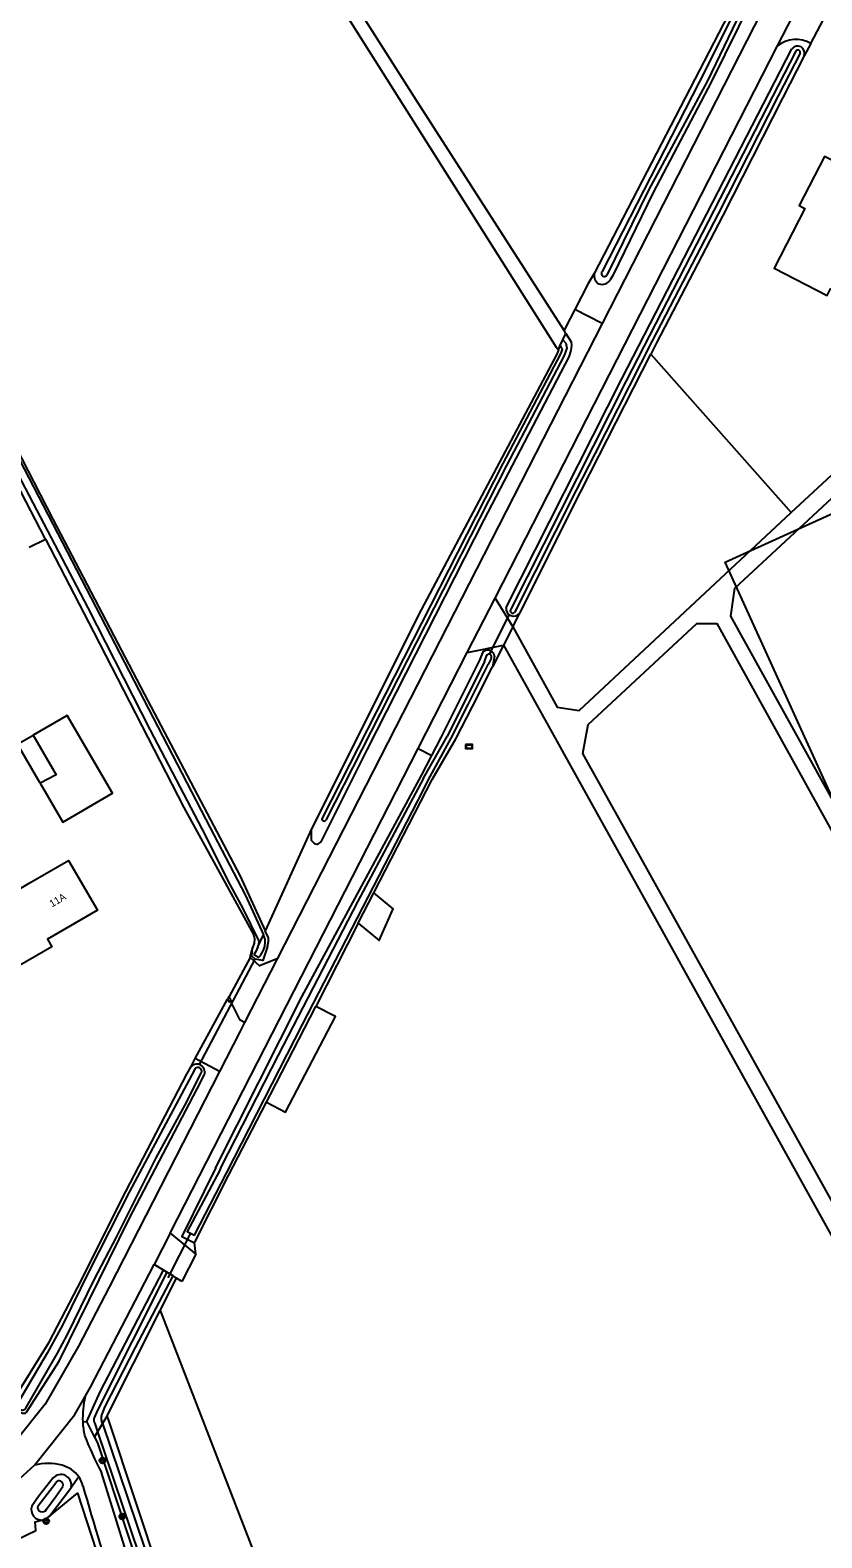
# Model space of a CAD drawing. Extents: x 141000 to 143000, y 400580 to 403500.
# Drawn here: x 141610 to 141719.9, y 402801.5 to 403010.7 of the extents above; entities that cross this region are included whole.
import ezdxf

# ---------------------------------------------------------------- set-up
doc = ezdxf.new("R2010")
doc.units = 0
for name, color, linetype in [('gg-afsc-draadraster', 7, 'Continuous'), ('gg-afsc-erfafscheiding', 7, 'Continuous'), ('gg-afsc-muur', 7, 'Continuous'), ('gg-anno-huisnummerreeks BGT', 7, 'Continuous'), ('gg-bbg-bijgebouw', 7, 'Continuous'), ('gg-bbg-hoofdgebouw', 7, 'Continuous'), ('gg-bbg-luifel en loopbrug', 7, 'Continuous'), ('gg-knt-bronhoudergrens', 7, 'Continuous'), ('gg-knt-onverhard', 7, 'Continuous'), ('gg-knt-verharding', 7, 'Continuous'), ('gg-knt-verharding nz', 7, 'Continuous'), ('gg-kntw-bovenkant insteek waterloop', 7, 'Continuous'), ('gg-kntw-waterlijn', 7, 'Continuous'), ('gg-kwrk-duiker nz buis', 7, 'Continuous'), ('gt-bbg-plantopografie pand', 7, 'Continuous'), ('gt-grn-groengrens', 7, 'Continuous'), ('gt-grn-vlakafsluiter', 7, 'Continuous'), ('gt-grn-weggrens', 7, 'Continuous'), ('gt-symb-boom', 7, 'Continuous'), ('gt-symb-informatiebord', 7, 'Continuous')]:
    doc.layers.add(name, color=color, linetype=linetype)

# ---------------------------------------------------------------- blocks, each defined once
blk = doc.blocks.new('gt0-IBORD')
at = {"layer": 'gt-symb-informatiebord'}
blk.add_lwpolyline([(-0.5, 0.29), (-0.5, -0.29), (0.5, -0.29), (0.5, 0.29), (-0.5, 0.29)], dxfattribs=at)
blk.add_lwpolyline([(-0.42, -0.21), (0.42, -0.21), (0.42, 0.21), (-0.42, 0.21)], close=True, dxfattribs=at)
blk = doc.blocks.new('gt0-BOOM')
at = {"layer": 'gt-symb-boom'}
for radius in [0.4, 0.2]:
    blk.add_circle((0, 0), radius, dxfattribs=at)

msp = doc.modelspace()

# ---------------------------------------------------------------- linework, layer by layer
at = {"layer": 'gg-afsc-draadraster'}
for p, q in [((141713.99, 403026.62), (141688.28, 402976.92)), ((141685.59, 402971.93), (141684.31, 402969.43))]:
    msp.add_line(p, q, dxfattribs=at)
for points in [[(141688.28, 402976.92), (141687.42, 402975.51), (141685.59, 402971.93)], [(141612.7, 402804.54), (141616.6, 402807.72), (141625.72, 402779.73), (141633.21, 402756.1), (141638.94, 402738.23), (141640.79, 402731.57), (141644.03, 402724.11)], [(141604.8, 402800.35), (141605.26, 402800.84), (141606.79, 402800.61), (141610.8, 402802.57), (141610.7, 402803.77), (141611.78, 402804.01)], [(141611.78, 402804.01), (141612.14, 402804.09), (141612.7, 402804.54)]]:
    msp.add_lwpolyline(points, dxfattribs=at)
at = {"layer": 'gg-afsc-erfafscheiding'}
for p, q in [((141718.31, 403008.83), (141717.4, 403007.11)), ((141609.88, 402938.93), (141612.14, 402940.08)), ((141632.36, 402866.93), (141632.94, 402868))]:
    msp.add_line(p, q, dxfattribs=at)
at = {"layer": 'gg-afsc-muur'}
for points in [[(141637.8, 402876), (141637.9, 402876.07), (141637.62, 402876.61)], [(141637.42, 402876.24), (141637.61, 402875.88), (141637.8, 402876)]]:
    msp.add_lwpolyline(points, dxfattribs=at)
at = {"layer": 'gg-bbg-bijgebouw'}
for points in [[(141611.4, 402906.19), (141614.55, 402900.8), (141621.46, 402904.81), (141615.16, 402915.61), (141610.45, 402912.88)], [(141610.45, 402912.88), (141613.65, 402907.36), (141611.4, 402906.19)]]:
    msp.add_lwpolyline(points, dxfattribs=at)
at = {"layer": 'gg-bbg-hoofdgebouw'}
for points in [[(141726.62, 402985.52), (141728.4, 402988.97), (141720.24, 402993.15), (141716.71, 402986.32), (141717.5, 402985.91), (141713.24, 402977.65), (141720.6, 402973.86), (141721.12, 402974.87)], [(141608.18, 402890.65), (141607.89, 402891.15), (141607.95, 402891.18), (141609.91, 402892.32), (141615.34, 402895.48), (141619.35, 402888.58), (141612.45, 402884.56), (141613.03, 402883.52), (141603.67, 402878.14), (141599.76, 402884.8), (141608.58, 402889.96), (141608.18, 402890.65)]]:
    msp.add_lwpolyline(points, dxfattribs=at)
at = {"layer": 'gg-bbg-luifel en loopbrug'}
msp.add_lwpolyline([(141611.4, 402906.19), (141608.25, 402911.61), (141610.45, 402912.88)], dxfattribs=at)
at = {"layer": 'gg-knt-bronhoudergrens'}
for p, q in [((141676.97, 402927.88), (141677.95, 402929.8)), ((141675.69, 402925.35), (141674.18, 402922.37)), ((141649.05, 402899.9), (141642.65, 402885.72)), ((141616.77, 402809.98), (141615.74, 402808.58))]:
    msp.add_line(p, q, dxfattribs=at)
for points in [[(141655.55, 402886.8), (141658.45, 402884.39), (141660.37, 402888.79), (141657.71, 402891.01)], [(141642.81, 402861.96), (141645.46, 402860.58), (141652.38, 402873.85), (141649.64, 402875.25)], [(141628.08, 402833.06), (141641.55, 402798.18), (141665.65, 402741.9)]]:
    msp.add_lwpolyline(points, dxfattribs=at)
at = {"layer": 'gg-knt-onverhard'}
for p, q in [((141696.12, 402965.71), (141715.59, 402943.74)), ((141675.69, 402925.35), (141741.01, 402807.69))]:
    msp.add_line(p, q, dxfattribs=at)
for points in [[(141739.81, 402870.58), (141707.24, 402929.36), (141707.8, 402933.27), (141723.12, 402947.49), (141726.14, 402947.03), (141781.13, 402847.8), (141780.4, 402843.99), (141743.73, 402812.88), (141740.9, 402812.93), (141686.71, 402910.32), (141687.42, 402914.35), (141702.51, 402928.36), (141705.27, 402928.37), (141737.88, 402869.52)], [(141676.97, 402927.88), (141683.13, 402916.76), (141686.17, 402916.28), (141715.59, 402943.74)], [(141644.29, 402881.85), (141641.85, 402880.86), (141640.57, 402882.04)]]:
    msp.add_lwpolyline(points, dxfattribs=at)
for centre, radius, start, end in [((141613.49, 402807.74), 3.98, 14.7133, 34.3772), ((142557.08, 403081.96), 978.66, 196.21103, 198.16646)]:
    msp.add_arc(centre, radius, start, end, dxfattribs=at)
at = {"layer": 'gg-knt-verharding'}
for p, q in [((141713.71, 403008.47), (141724.6, 403029.76)), ((141718.93, 403027.79), (141689.37, 402969.99)), ((141718.31, 403008.83), (141726.5, 403024.32)), ((141674.52, 402931.89), (141713.71, 403008.47)), ((141689.37, 402969.99), (141644.29, 402881.85)), ((141670.65, 402924.33), (141674.52, 402931.89)), ((141674.52, 402931.89), (141676.97, 402927.88)), ((141676.97, 402927.88), (141675.69, 402925.35)), ((141670.65, 402924.33), (141675.69, 402925.35)), ((141663.84, 402911), (141670.65, 402924.33)), ((141629.45, 402843.8), (141663.84, 402911)), ((141644.29, 402881.85), (141639.78, 402873.03)), ((141639.78, 402873.03), (141639.12, 402871.73)), ((141639.12, 402871.73), (141636.3, 402866.21)), ((141636.3, 402866.21), (141632.94, 402868)), ((141629.45, 402843.8), (141633.03, 402840.87)), ((141628.51, 402838.67), (141627.22, 402839.45)), ((141628.99, 402838.37), (141628.51, 402838.67)), ((141629.85, 402837.85), (141628.99, 402838.37)), ((141630.35, 402837.55), (141629.85, 402837.85)), ((141631.08, 402837.1), (141630.35, 402837.55))]:
    msp.add_line(p, q, dxfattribs=at)
for points in [[(141715.59, 402943.74), (141752.27, 402977.7), (141766.41, 402991.54)], [(141639.78, 402873.03), (141639.18, 402873.36), (141637.8, 402876)], [(141636.3, 402866.21), (141621.01, 402836.32), (141616.71, 402828.12), (141612.12, 402820.08), (141608.07, 402815.01)], [(141617.66, 402821.13), (141618.42, 402822.45), (141624.65, 402834.43), (141627.22, 402839.45)], [(141574.46, 402791.49), (141581.55, 402794.34), (141591.69, 402798.64), (141601.51, 402803.82), (141604.92, 402806.58), (141606.17, 402807.59), (141606.55, 402807.93), (141610.62, 402811.61)], [(141645.32, 402730.78), (141642.92, 402738.05), (141633.75, 402766.89), (141624.16, 402796.89), (141619.91, 402810.58)]]:
    msp.add_lwpolyline(points, dxfattribs=at)
for centre, radius, start, end in [((141716.27, 403005.37), 4.02, 59.4668, 129.5325), ((141629.66, 402818.22), 12.35, 166.3908, 182.8086), ((141629.61, 402818.21), 12.3, 182.7573, 191.5305), ((141668.93, 402835.99), 55.22, 201.5092, 207.4087), ((141612.51, 402804.02), 7.82, 75.563, 103.9896), ((141613.47, 402807.73), 3.99, 34.3561, 75.6799)]:
    msp.add_arc(centre, radius, start, end, dxfattribs=at)
at = {"layer": 'gg-knt-verharding nz'}
msp.add_line((141629.45, 402843.8), (141627.22, 402839.45), dxfattribs=at)
at = {"layer": 'gg-kntw-bovenkant insteek waterloop'}
for p, q in [((141684.34, 402968.61), (141684.09, 402969)), ((141667.05, 402912.55), (141672.4, 402923.27)), ((141672.4, 402923.27), (141672.9, 402924.5)), ((141674.45, 402923.82), (141674.18, 402922.37)), ((141665.74, 402910.03), (141667.05, 402912.55)), ((141665.78, 402906.73), (141669.1, 402912.36)), ((141664.34, 402907.35), (141665.74, 402910.03)), ((141657.71, 402891.01), (141665.78, 402906.73)), ((141655.55, 402886.8), (141657.71, 402891.01)), ((141655.55, 402886.8), (141649.64, 402875.25)), ((141637.53, 402851.81), (141642.81, 402861.96)), ((141632.81, 402842.43), (141637.53, 402851.81)), ((141628.08, 402833.06), (141630.35, 402837.55)), ((141620.73, 402818.46), (141628.08, 402833.06)), ((141618.96, 402815.54), (141617.91, 402817.67)), ((141612.7, 402804.54), (141615.74, 402808.58)), ((141615.74, 402808.58), (141615.74, 402808.63))]:
    msp.add_line(p, q, dxfattribs=at)
for points in [[(141717.37, 403029.19), (141717.31, 403028.8), (141712.14, 403018.92), (141704.49, 403003.47), (141696.46, 402988.14), (141690.84, 402976.65), (141690.51, 402976.04)], [(141684.09, 402969), (141663.63, 403000.93), (141647.1, 403026.91)], [(141648.3, 403021.6), (141683, 402966.71), (141683.3, 402966.34)], [(141676.07, 402930.59), (141692.13, 402962.31), (141715.7, 403008.09)], [(141717.4, 403007.11), (141714.38, 403001.25), (141706.08, 402984.87), (141696.91, 402967.27), (141696.12, 402965.71)], [(141684.34, 402968.61), (141685.06, 402967.42), (141685.12, 402966.98), (141685.04, 402966.24), (141684.77, 402965.37), (141672.98, 402942.73), (141656.75, 402910.84), (141651.43, 402900.2), (141650.37, 402898.08), (141649.82, 402897.72), (141649.62, 402897.76), (141649.39, 402897.93), (141649.07, 402898.27), (141649.05, 402899.9)], [(141600.9, 402966.6), (141613.17, 402942.83), (141625.82, 402918.6), (141639.14, 402893.32), (141642.65, 402885.72)], [(141683.3, 402966.34), (141683.14, 402965.83), (141664.29, 402930.24), (141649.05, 402899.9)], [(141677.95, 402929.8), (141686.37, 402946.57), (141688.93, 402951.59), (141696.12, 402965.71)], [(141612.14, 402940.08), (141601.14, 402961.25)], [(141612.14, 402940.08), (141618.83, 402927.22), (141631.35, 402902.86), (141641.01, 402885.23), (141641.15, 402884.62), (141641.11, 402884.04), (141640.88, 402883.36)], [(141669.1, 402912.36), (141671.37, 402916.84), (141674.18, 402922.37)], [(141635.74, 402852.82), (141647.72, 402876.56), (141664.34, 402907.35)], [(141642.94, 402883.55), (141643.07, 402884.26), (141643.09, 402884.76), (141642.65, 402885.72)], [(141642.94, 402883.55), (141642.29, 402881.6), (141641.23, 402881.79), (141640.78, 402882.23), (141640.88, 402883.36)], [(141642.81, 402861.96), (141643.37, 402863.04), (141649.64, 402875.25)], [(141608.01, 402821.12), (141612.67, 402828.65), (141616.63, 402836.32), (141623.31, 402849.55), (141631.77, 402865.85), (141632.36, 402866.93)], [(141608.01, 402821.12), (141607.62, 402820.38), (141607.67, 402819.88), (141608.45, 402819.07), (141608.95, 402818.82), (141609.37, 402818.82), (141609.54, 402818.95), (141614.07, 402826.02), (141623.78, 402845.8), (141633.19, 402863.79), (141634.22, 402865.8)], [(141635.74, 402852.82), (141631.05, 402843.32), (141632.81, 402842.43)], [(141617.91, 402817.67), (141619.73, 402821.8), (141628.51, 402838.67)], [(141651.38, 402729.76), (141646.08, 402742.03), (141620.99, 402817.67), (141620.73, 402818.46)], [(141618.96, 402815.54), (141618.97, 402815.51), (141619.36, 402814.72), (141631.55, 402777.82), (141647.88, 402726.79)], [(141613.21, 402809.85), (141611.19, 402807.26), (141610.25, 402805.91)]]:
    msp.add_lwpolyline(points, dxfattribs=at)
for centre, radius, start, end in [((141716.47, 403007.47), 0.996, 339.1586, 141.0625), ((141689.7, 402976.67), 1.44, 170.3312, 237.2632), ((141689.37, 402976.7), 1.31, 249.8338, 329.8127), ((141677.11, 402930.42), 1.05, 171.1347, 323.5607), ((141673.48, 402923.7), 0.983, 58.8453, 125.8035), ((141673.48, 402923.7), 0.985, 7.26, 58.6697), ((141633.13, 402866.11), 1.13, 343.9303, 133.4651), ((141614.28, 402808.84), 1.47, 351.6292, 136.667), ((141611.61, 402805.43), 1.44, 160.6251, 276.7678)]:
    msp.add_arc(centre, radius, start, end, dxfattribs=at)
at = {"layer": 'gg-kntw-waterlijn'}
for p, q in [((141683.93, 402967.72), (141684.34, 402968.61)), ((141683.3, 402966.34), (141683.56, 402966.9)), ((141673.04, 402923.07), (141667.86, 402912.7)), ((141673.04, 402923.07), (141673.43, 402924.04)), ((141673.98, 402923.49), (141673.57, 402922.68)), ((141664.6, 402906.89), (141667.86, 402912.7)), ((141665.23, 402906.64), (141668.41, 402912.46)), ((141641.69, 402882.03), (141641.07, 402882.41)), ((141618.98, 402817.39), (141619.37, 402816.23)), ((141620.06, 402817.37), (141619.91, 402817.82)), ((141611.07, 402805.93), (141613.57, 402809.17))]:
    msp.add_line(p, q, dxfattribs=at)
for points in [[(141538.27, 403359.59), (141538.33, 403359.06), (141541.47, 403322.87), (141544.59, 403292.28), (141547, 403265.98), (141553.51, 403196.86), (141560.15, 403123.6), (141563.75, 403081.59), (141565.25, 403062.99), (141566.36, 403054.61), (141566.82, 403051.93), (141568.25, 403046.81), (141576.99, 403021.8), (141586.69, 402994.31), (141588.36, 402989.96), (141589.28, 402987.92), (141591.05, 402984.79), (141602.47, 402962.69), (141634.38, 402901.18), (141639.91, 402890.64), (141642.38, 402885.16)], [(141715.78, 403029.25), (141715.55, 403028.84), (141702.82, 403003.43), (141689.37, 402977.2)], [(141716.49, 403028.81), (141711.5, 403019.25), (141703.99, 403003.65), (141695.81, 402988.47), (141690.04, 402976.67)], [(141716.25, 403007.73), (141692.72, 402962.01), (141676.7, 402930.36)], [(141716.84, 403007.46), (141713.79, 403001.55), (141705.49, 402985.18), (141696.32, 402967.57), (141688.34, 402951.89), (141685.78, 402946.86), (141677.2, 402929.87)], [(141683.56, 402966.9), (141683.85, 402966.38), (141683.62, 402965.78), (141675.62, 402950.56), (141650.54, 402901.35)], [(141683.93, 402967.72), (141684.34, 402967.23), (141684.48, 402966.56), (141684.11, 402965.53), (141676.11, 402950.3), (141651.03, 402901.1)], [(141602.15, 402960.72), (141618.03, 402930.53), (141626.67, 402913.56), (141633.82, 402899.9), (141637.76, 402892.05), (141639.55, 402888.81), (141641.71, 402884.37), (141641.73, 402884.2), (141641.69, 402883.87), (141641.59, 402883.51)], [(141668.41, 402912.46), (141670.77, 402917.14), (141673.57, 402922.68)], [(141664.6, 402906.89), (141655.48, 402889.86), (141644.42, 402868.5), (141636.49, 402852.95), (141636.35, 402852.51)], [(141637.26, 402852.12), (141647.82, 402872.73), (141664.57, 402905.21), (141665.23, 402906.64)], [(141641.69, 402882.03), (141641.97, 402882.32), (141642.35, 402882.97), (141642.56, 402883.54), (141642.63, 402884.2), (141642.61, 402884.53), (141642.53, 402884.82), (141642.38, 402885.16)], [(141641.59, 402883.51), (141641.33, 402882.88), (141641.07, 402882.41)], [(141632.81, 402866.43), (141623.77, 402849.47), (141618.2, 402838.55), (141614.57, 402831.14), (141612.39, 402827.14), (141608.27, 402820.16), (141608.3, 402819.68), (141608.61, 402819.32), (141608.97, 402819.22), (141609.22, 402819.35), (141609.49, 402819.62), (141613.81, 402827.15), (141615.19, 402829.74), (141618.9, 402837.32), (141622.02, 402843.24), (141624.85, 402848.99), (141627.53, 402854.22), (141631.49, 402861.51), (141633.73, 402865.97)], [(141636.35, 402852.51), (141631.83, 402844.02), (141632.82, 402843.51), (141637.26, 402852.12)], [(141628.99, 402838.37), (141619.38, 402819.24), (141618.89, 402818.16)], [(141619.91, 402818.47), (141620, 402818.69), (141620.42, 402819.76), (141624.65, 402827.95), (141629.85, 402837.85)], [(141619.37, 402816.23), (141633.15, 402775.45), (141648.82, 402727.59)], [(141620.06, 402817.37), (141634.1, 402775.76), (141649.64, 402728.29)], [(141612.28, 402805.49), (141613.57, 402807.26), (141614.56, 402808.67)]]:
    msp.add_lwpolyline(points, dxfattribs=at)
for centre, radius, start, end in [((141716.54, 403007.59), 0.321, 336.3901, 154.6333), ((141689.7, 402976.93), 0.429, 140.4671, 322.8808), ((141676.98, 402930.14), 0.353, 142.2382, 310.0718), ((141673.66, 402923.72), 0.393, 74.3234, 126.8754), ((141673.66, 402923.72), 0.394, 324.2445, 74.4193), ((141650.78, 402901.21), 0.275, 149.7996, 336.1387), ((141633.3, 402866.26), 0.523, 325.3491, 160.7298), ((141620.01, 402817.91), 1.15, 167.2566, 206.5525), ((141621.06, 402818.14), 1.19, 164.4001, 195.7773), ((141614.05, 402808.9), 0.554, 336.2316, 150.7309), ((141611.7, 402805.77), 0.644, 164.9764, 334.3401)]:
    msp.add_arc(centre, radius, start, end, dxfattribs=at)
at = {"layer": 'gg-kwrk-duiker nz buis'}
for p, q in [((141673.77, 402924.1), (141676.53, 402929.6)), ((141633.49, 402867.1), (141641.25, 402881.79)), ((141629.16, 402837.6), (141632.32, 402843.77))]:
    msp.add_line(p, q, dxfattribs=at)
at = {"layer": 'gt-bbg-plantopografie pand'}
msp.add_lwpolyline([(141724.04, 402944.88), (141740.02, 402909.85), (141722.4, 402901.82), (141706.43, 402936.85), (141724.04, 402944.88)], dxfattribs=at)
at = {"layer": 'gt-grn-groengrens'}
for p, q in [((141689.37, 402969.99), (141685.59, 402971.93)), ((141684.31, 402969.43), (141684.09, 402969)), ((141663.84, 402911), (141665.74, 402910.03)), ((141640.57, 402882.04), (141640.88, 402883.36)), ((141633.03, 402840.87), (141632.81, 402842.43)), ((141617.33, 402817.62), (141617.91, 402817.67))]:
    msp.add_line(p, q, dxfattribs=at)
at = {"layer": 'gt-grn-vlakafsluiter'}
for p, q in [((141683.56, 402966.9), (141683.93, 402967.72)), ((141641.59, 402883.51), (141642.38, 402885.16)), ((141640.57, 402882.04), (141637.62, 402876.61)), ((141637.62, 402876.61), (141637.42, 402876.24)), ((141632.94, 402868), (141637.42, 402876.24)), ((141633.03, 402840.87), (141631.08, 402837.1)), ((141620.73, 402818.46), (141620.06, 402817.37)), ((141619.37, 402816.23), (141618.96, 402815.54)), ((141620.06, 402817.37), (141619.37, 402816.23))]:
    msp.add_line(p, q, dxfattribs=at)
at = {"layer": 'gt-grn-weggrens'}
msp.add_lwpolyline([(141610.62, 402811.61), (141616.23, 402818.66), (141617.66, 402821.13)], dxfattribs=at)

# ---------------------------------------------------------------- block references
at = {"layer": 'gt-symb-boom'}
for p in [(141620.05, 402812.24), (141612.25, 402803.84), (141622.8, 402804.49)]:
    msp.add_blockref('gt0-BOOM', p, dxfattribs=at)
at = {"layer": 'gt-symb-informatiebord'}
msp.add_blockref('gt0-IBORD', (141670.91, 402911.29), dxfattribs=at)

# ---------------------------------------------------------------- texts
at = {"layer": 'gg-anno-huisnummerreeks BGT'}
msp.add_text('11A', height=1, rotation=30.3, dxfattribs=at).set_placement((141613.06, 402888.96))

doc.saveas('drawing.dxf')
